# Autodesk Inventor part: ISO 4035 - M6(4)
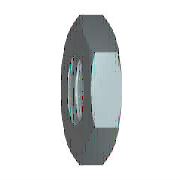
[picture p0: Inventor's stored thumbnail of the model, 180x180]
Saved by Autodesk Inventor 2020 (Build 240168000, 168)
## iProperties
Created: 2019-01
Part Number: ISO 4035 - M6(4)
Material: Nerezová ocel 440C
Description: Šestihranné matice nízké se zkosením – Výrobní třída A a B
Document SubType Name: Modeling
Standard: ISO 4035
Designer: doma
Standard Revision: Fourth edition 2012-12-15
Standards Organization: ISO
Language: cs-CZ
Size Designation: M6
Categories: <MemberInstance><Categories><Category DisplayName="Spojovací materiál" InternalName="e4da775c-781d-43d5-af7c-5136215cf5a6" Mnemonic="FSTN"><Category DisplayName
Density: 7.75 g/cm^3
Appearance: Pololeštěná
IsCustomPart: 0
Author: doma
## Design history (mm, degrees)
sketch "Náčrt1"
  geometry: L1 (-5.774, 0)-(-2.887, 5); L2 (-2.887, 5)-(2.887, 5); L3 (2.887, 5)-(5.774, 0); L4 (5.774, 0)-(2.887, -5); L5 (2.887, -5)-(-2.887, -5); L6 (-2.887, -5)-(-5.774, 0); 2 further points
  constraints: 12 end point, 1 coincident, 1 horizontal, 11 other
  dimensions: "d0" = 11.54701 distance of L3.end L1.start (= 1.1547 x SW)
extrude "Těleso" new body sketch "Náčrt1" distance "d1" = 3.2 (= KOH); taper "d2" = 0 deg
sketch "Náčrt2"
  geometry: L1 (0, 2.887)-(0, 5.774) reference; L2 (0, 5.774)-(3.2, 5.774) reference; L3 (3.2, 2.887)-(3.2, 5.774) reference; L4 (-0.64, 0)-(3.84, 0) reference; L5 (0.764, 5.774)-(0, 4.45); L6 (2.436, 5.774)-(3.2, 4.45)
  constraints: 4 end point, 4 point on line
  dimensions: "d3" = 30 deg angle of L1 L5 (= ANG1); "d4" = 30 deg angle of L3 L6 (= ANG2); "d5" = 8.9 diameter of L5.end L4 (= SW0); "d6" = 8.9 diameter of L6.end L4 (= SW01)
revolve "Zkosení1" sketch "Náčrt2" stored, may be unused: angle "d7" = 90 deg
sketch "Náčrt3"
  geometry: 4 further points
  constraints: 1 coincident, 1 other
hole "Závit" sketch "Náčrt3" at (0, 0) diameter "d25" = 4.917; stored, may be unused: countersink angle "d29" = 82 deg, drill point angle "d31" = 118 deg; dims "d26" = 6, "d27" = 4, "d28" = 2, "d30" = 8
workaxis "Work Axis1"
workplane "Work Plane1"
body "Solid1"
chamfer "Zkosení2" distance "d8" = 0.54127 (= -0.5 x GD1 + 0.5 x NND); stored, may be unused: angle "d9" = 30 deg, second distance "d40" = 0.54127 (= -0.5 x GD1 + 0.5 x NND)
chamfer "Zkosení3" distance "d10" = 0.54127 (= -0.5 x GD1 + 0.5 x NND); stored, may be unused: angle "d11" = 30 deg, second distance "d41" = 0.54127 (= -0.5 x GD1 + 0.5 x NND)
other parameters: "ANG1" = 30 deg [user parameter; used in 1 equation term], "ANG2" = 30 deg [user parameter; used in 1 equation term], "NND" = 6 [user parameter; used in 4 equation terms], "KOH" = 3.2 [user parameter; used in 1 equation term], "SW0" = 8.9 [user parameter; used in 2 equation terms], "SW01" = 8.9 (= SW0) [user parameter; used in 1 equation term], "GD1" = 4.91747 (computed from THREADDIA, PTC, TOA) [user parameter; used in 4 equation terms], "d13" = 0, "d14" = 0, "d39" = 0, "d42" = 0, "GUL" = 0.54127 (= 0.541266 x PTC) [user parameter], "THREADDIA" = 6 [user parameter; used in 1 equation term], "TOA" = 30 deg [user parameter; used in 1 equation term], "PTC" = 1 [user parameter; used in 4 equation terms], "E0" = 11.55 (= 1.155 x SW) [user parameter], "GAL" = 0.54127 (= 0.541266 x PTC) [user parameter]
